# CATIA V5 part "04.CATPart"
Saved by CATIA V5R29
Part number: 04
Bounding box of the stored display mesh (mm): x -24 to 24, y -5 to 5, z 0 to 16
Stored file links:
  C:\Users\FERIDUN\Desktop\montaj3\04.CATPart
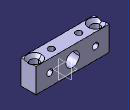
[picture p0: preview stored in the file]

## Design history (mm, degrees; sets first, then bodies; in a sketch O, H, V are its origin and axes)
Body1 (main body)
  Sketch1 on xy-plane, origin (0, 0, 0), H (1, 0, 0), V (0, 1, 0)
    line L1 (24, 5) -> (24, -5)
    line L2 (24, -5) -> (-24, -5)
    line L3 (-24, -5) -> (-24, 5)
    line L4 (-24, 5) -> (24, 5)
    distance L1 L3 = 48
    distance L2 L4 = 10
    vertical: L1 V, L3 V
    horizontal: L2 H, L4 H
    equidistance: L1 L3 O, L2 L4 O
  Pad1: profile Sketch1, direction (0, 0, 1), length 16
  Sketch2 on end face of Pad1, origin (19.0347, -0.7684, 16), H (1, 0, 0), V (0, 1, 0)
    point P1 (0.9653, 0.7684)
    reference intersected line E1 through (0, 0.7684) direction (-1, 0) from zx-plane
    reference intersected line E2 through (-19.0347, 0) direction (0, 1) from yz-plane
    distance P1 E2 = 20
    coincidence: P1 E1
  Hole1: placed by Sketch2, at (20, 0, 16) direction (0, 0, -1), diameter 5.5, through (limit type 6), countersink depth 2, countersink angle 90
  Mirror1: of Hole1, about yz-plane
  Sketch3 on end face of Pad1, origin (8.346, 0.2721, 16), H (1, 0, 0), V (0, 1, 0)
    point P1 (0.654, -0.2721)
    reference intersected line E1 through (0, -0.2721) direction (-1, 0) from zx-plane
    reference intersected line E2 through (-8.346, 0) direction (0, 1) from yz-plane
    distance P1 E2 = 9
    coincidence: P1 E1
  Hole2: placed by Sketch3, at (9, 0, 16) direction (0, 0, -1), diameter 4, through (limit type 6)
  Mirror2: of Hole2, about yz-plane
  Sketch4 on face of Pad1 from Sketch1.L4, origin (8.8685, 5, 8.9146), H (1, 0, 0), V (0, 0, -1)
    point P1 (6.1315, 0.9146)
    reference intersected line E1 through (-8.8685, 0) direction (0, 1) from yz-plane
    reference projected line E2 (15.1315, 8.9146) -> (-32.8685, 8.9146) from edge [start face of Pad1 | face of Pad1 from Sketch1.L4]
    distance E1 P1 = 15
    distance P1 E2 = 8
  Hole3: placed by Sketch4, at (15, 5, 8) direction (0, -1, 0), diameter 4, through (limit type 6)
  Mirror3: of Hole3, about yz-plane
  Sketch5 on face of Pad1 from Sketch1.L4, origin (0.194, 5, 8), H (1, 0, 0), V (0, 0, -1)
    point P1 (-0.194, 0)
    reference intersected line E1 through (-0.194, 0) direction (0, 1) from yz-plane
    reference intersected line E2 through (0, 8) direction (1, 0) from xy-plane
    distance E2 P1 = 8
    coincidence: E1 P1
  Hole4: placed by Sketch5, at (0, 5, 8) direction (0, -1, 0), diameter 8.917, through (limit type 6), threaded "M10x1", thread diameter 10, thread depth 10, pitch 1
